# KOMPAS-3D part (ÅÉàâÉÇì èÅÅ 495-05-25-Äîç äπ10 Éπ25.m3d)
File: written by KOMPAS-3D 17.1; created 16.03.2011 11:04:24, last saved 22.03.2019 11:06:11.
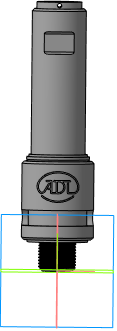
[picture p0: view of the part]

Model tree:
1. Плоскость XY
2. Плоскость ZX
3. Плоскость ZY
4. Ось X
5. Ось Y
6. Ось Z
7. Начало координат
8. Операция без истории:2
